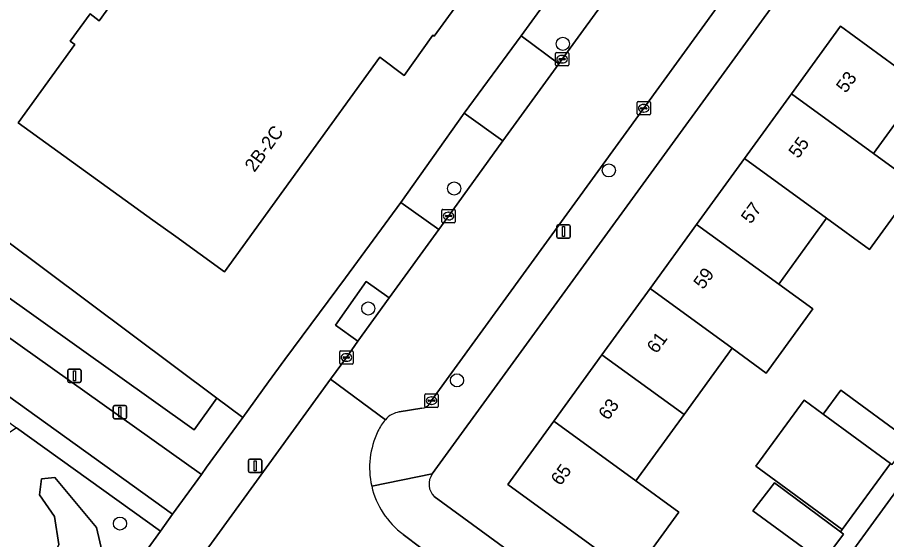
# Model space of a CAD drawing. Extents: x 159674 to 160531, y 382172 to 382904.
# Drawn here: x 160035.6 to 160100.6, y 382527.2 to 382566.2 of the extents above; entities that cross this region are included whole.
import ezdxf

# ---------------------------------------------------------------- set-up
doc = ezdxf.new("R2010")
doc.units = 0
for name, color, linetype in [('IMGEO_Boom', 7, 'Continuous'), ('IMGEO_Erf', 7, 'Continuous'), ('IMGEO_Fietspad_gesloten', 7, 'Continuous'), ('IMGEO_Groenvoorziening', 7, 'Continuous'), ('IMGEO_Kolk', 7, 'Continuous'), ('IMGEO_Lichtmast', 7, 'Continuous'), ('IMGEO_Pand', 7, 'Continuous'), ('IMGEO_Pand_nummerreeks', 7, 'Continuous'), ('IMGEO_Rijbaan_lokaal_open', 7, 'Continuous'), ('IMGEO_Voetpad_open', 7, 'Continuous')]:
    doc.layers.add(name, color=color, linetype=linetype)

msp = doc.modelspace()

# ---------------------------------------------------------------- linework, layer by layer
at = {"layer": 'IMGEO_Boom'}
for centre in [(160076.364, 382564.175), (160079.803, 382554.724), (160068.243, 382553.373), (160061.83, 382544.417), (160068.457, 382539.049), (160043.275, 382528.35)]:
    msp.add_circle(centre, 0.489, dxfattribs=at)
at = {"layer": 'IMGEO_Erf'}
for points in [[(159987.625, 382596.74), (159998.32, 382576.572), (160012.158, 382566.305), (160014.085, 382564.875), (160015.556, 382563.784), (160018.977, 382561.245), (160021.814, 382559.14), (160050.522, 382537.716), (160052.445, 382536.281), (160054.378, 382538.936), (160055.599, 382540.613), (160060.131, 382546.714), (160064.26, 382552.334), (160068.989, 382558.995), (160073.24, 382564.766), (160078.977, 382572.654), (160139.025, 382655.211)], [(160094.261, 382570.107), (160066.611, 382532.056)], [(160068.292, 382566.873), (160066.759, 382564.747), (160066.664, 382564.815), (160064.516, 382561.824), (160062.689, 382563.177), (160051.094, 382547.163), (160047.457, 382549.785), (160045.739, 382551.011), (160035.664, 382558.271), (160039.913, 382564.137), (160039.563, 382564.384), (160041.044, 382566.417), (160041.727, 382565.89), (160044.328, 382569.516)], [(160066.763, 382530.365), (160087.821, 382514.988), (160090.131, 382518.165), (160085.126, 382521.804), (160086.631, 382523.874), (160089.441, 382521.831), (160091.507, 382524.672), (160093.702, 382523.077), (160095.576, 382525.656), (160090.568, 382529.296), (160092.172, 382531.385), (160097.103, 382527.733), (160097.235, 382527.911), (160090.777, 382532.632), (160094.387, 382537.572), (160095.808, 382536.513), (160097.141, 382538.309), (160102.285, 382534.528), (160106.42, 382540.296)], [(160103.851, 382534.341), (160097.038, 382524.967), (160099.595, 382523.109), (160097.556, 382520.304), (160100.009, 382518.521), (160104.902, 382514.966)]]:
    msp.add_lwpolyline(points, dxfattribs=at)
msp.add_lwpolyline([(160099.269, 382548.826), (160096.071, 382551.151), (160092.496, 382546.232), (160095.042, 382544.381), (160091.565, 382539.597), (160089.018, 382541.448), (160085.42, 382536.499), (160081.824, 382531.551), (160085.04, 382529.214), (160081.597, 382524.477), (160078.381, 382526.815), (160072.249, 382531.273), (160075.691, 382536.008), (160079.288, 382540.956), (160082.886, 382545.905), (160086.364, 382550.69), (160089.94, 382555.608), (160093.458, 382560.448), (160097.119, 382565.484), (160103.251, 382561.027), (160099.59, 382555.99), (160102.783, 382553.66)], close=True, dxfattribs=at)
msp.add_arc((160067.66, 382531.298), 1.294, 144.14958, 226.12318, dxfattribs=at)
at = {"layer": 'IMGEO_Fietspad_gesloten'}
msp.add_lwpolyline([(159965.641, 382587.946), (160000, 382563.056), (160014.622, 382552.464), (160047.21, 382529.047), (160049.355, 382532.03), (160024.648, 382549.576), (160016.688, 382555.291), (160013.417, 382557.659), (160011.839, 382558.801), (160000, 382567.372), (159974.626, 382585.74), (159973.843, 382586.307), (159971.861, 382587.698)], dxfattribs=at)
at = {"layer": 'IMGEO_Groenvoorziening'}
for points in [[(160018.977, 382561.245), (160015.556, 382563.784), (160014.917, 382562.902), (160016.424, 382561.811), (160013.417, 382557.659), (160016.688, 382555.291), (160024.648, 382549.576), (160049.355, 382532.03), (160049.733, 382532.555), (160052.445, 382536.281), (160050.522, 382537.716), (160048.808, 382535.362), (160016.765, 382558.19)], [(160018.977, 382561.245), (160016.765, 382558.19), (160048.808, 382535.362), (160050.522, 382537.716), (160021.814, 382559.14)], [(160063.381, 382545.206), (160061.676, 382546.441), (160059.381, 382543.178), (160061.047, 382541.977)], [(160046.298, 382527.781), (160035.555, 382535.501), (160030.156, 382531.864), (160025.451, 382528.695), (160031.388, 382519.807), (160030.964, 382519.524), (160027.973, 382517.526), (160027.284, 382517.066), (160028.729, 382514.78), (160030.117, 382512.584), (160030.328, 382510.79), (160028.033, 382508.833), (160030.233, 382505.553), (160043.699, 382524.182)], [(160038.458, 382522.749), (160039.667, 382522.672), (160041.192, 382523.779), (160042.017, 382525.919), (160041.518, 382528.053), (160038.419, 382531.785), (160037.41, 382531.706), (160037.273, 382530.494), (160038.38, 382528.872), (160038.714, 382526.8), (160037.895, 382525.055), (160038.027, 382523.295)], [(160038.458, 382522.749), (160038.027, 382523.295), (160037.895, 382525.055), (160038.714, 382526.8), (160038.38, 382528.872), (160037.273, 382530.494), (160037.41, 382531.706), (160038.419, 382531.785), (160041.518, 382528.053), (160042.017, 382525.919), (160041.192, 382523.779), (160039.667, 382522.672)]]:
    msp.add_lwpolyline(points, close=True, dxfattribs=at)
at = {"layer": 'IMGEO_Kolk'}
for p, q in [((160075.81, 382562.609), (160075.81, 382563.461)), ((160075.885, 382563.535), (160076.737, 382563.535)), ((160076.069, 382563.029), (160076.069, 382563.041)), ((160076.507, 382562.992), (160076.109, 382562.992)), ((160076.112, 382563.078), (160076.51, 382563.078)), ((160076.298, 382563.315), (160076.323, 382563.315)), ((160076.553, 382563.041), (160076.553, 382563.029)), ((160076.811, 382563.461), (160076.811, 382562.609)), ((160076.737, 382562.535), (160075.885, 382562.535)), ((160076.321, 382562.755), (160076.296, 382562.755)), ((160081.91, 382558.94), (160081.91, 382559.792)), ((160081.985, 382559.866), (160082.837, 382559.866)), ((160082.911, 382559.792), (160082.911, 382558.94)), ((160082.169, 382559.36), (160082.169, 382559.372)), ((160082.607, 382559.323), (160082.209, 382559.323)), ((160082.212, 382559.409), (160082.61, 382559.409)), ((160082.421, 382559.086), (160082.396, 382559.086)), ((160082.398, 382559.646), (160082.423, 382559.646)), ((160082.653, 382559.372), (160082.653, 382559.36)), ((160082.837, 382558.866), (160081.985, 382558.866)), ((160067.328, 382550.891), (160067.328, 382551.743)), ((160067.403, 382551.817), (160068.255, 382551.817)), ((160067.587, 382551.311), (160067.587, 382551.323)), ((160068.025, 382551.274), (160067.627, 382551.274)), ((160067.63, 382551.36), (160068.028, 382551.36)), ((160067.816, 382551.597), (160067.841, 382551.597)), ((160068.071, 382551.323), (160068.071, 382551.311)), ((160068.329, 382551.743), (160068.329, 382550.891)), ((160068.255, 382550.817), (160067.403, 382550.817)), ((160067.839, 382551.037), (160067.814, 382551.037)), ((160059.691, 382540.331), (160059.691, 382541.183)), ((160059.766, 382541.257), (160060.618, 382541.257)), ((160060.179, 382541.037), (160060.204, 382541.037)), ((160060.692, 382541.183), (160060.692, 382540.331)), ((160060.618, 382540.257), (160059.766, 382540.257)), ((160059.95, 382540.751), (160059.95, 382540.763)), ((160060.388, 382540.714), (160059.99, 382540.714)), ((160059.993, 382540.8), (160060.391, 382540.8)), ((160060.202, 382540.477), (160060.177, 382540.477)), ((160060.434, 382540.763), (160060.434, 382540.751)), ((160066.056, 382537.106), (160066.056, 382537.958)), ((160066.131, 382538.032), (160066.983, 382538.032)), ((160066.544, 382537.812), (160066.569, 382537.812)), ((160067.057, 382537.958), (160067.057, 382537.106)), ((160066.983, 382537.032), (160066.131, 382537.032)), ((160066.315, 382537.526), (160066.315, 382537.538)), ((160066.753, 382537.489), (160066.355, 382537.489)), ((160066.358, 382537.575), (160066.756, 382537.575)), ((160066.567, 382537.252), (160066.542, 382537.252)), ((160066.799, 382537.538), (160066.799, 382537.526))]:
    msp.add_line(p, q, dxfattribs=at)
for points in [[(160075.81, 382562.609), (160075.81, 382563.461)], [(160075.885, 382563.535), (160076.737, 382563.535)], [(160076.811, 382563.461), (160076.811, 382562.609)], [(160076.737, 382562.535), (160075.885, 382562.535)], [(160081.91, 382558.94), (160081.91, 382559.792)], [(160081.985, 382559.866), (160082.837, 382559.866)], [(160082.911, 382559.792), (160082.911, 382558.94)], [(160082.837, 382558.866), (160081.985, 382558.866)], [(160067.328, 382550.891), (160067.328, 382551.743)], [(160067.403, 382551.817), (160068.255, 382551.817)], [(160068.329, 382551.743), (160068.329, 382550.891)], [(160068.255, 382550.817), (160067.403, 382550.817)], [(160059.691, 382540.331), (160059.691, 382541.183)], [(160059.766, 382541.257), (160060.618, 382541.257)], [(160060.692, 382541.183), (160060.692, 382540.331)], [(160060.618, 382540.257), (160059.766, 382540.257)], [(160066.056, 382537.106), (160066.056, 382537.958)], [(160066.131, 382538.032), (160066.983, 382538.032)], [(160067.057, 382537.958), (160067.057, 382537.106)], [(160066.983, 382537.032), (160066.131, 382537.032)]]:
    msp.add_lwpolyline(points, dxfattribs=at)
for centre, radius, start, end in [((160075.887, 382563.459), 0.0765, 91.55205, 178.44795), ((160075.887, 382563.459), 0.0765, 91.55205, 178.44795), ((160076.109, 382563.038), 0.0403, 85.87752, 175.75265), ((160076.106, 382563.028), 0.0366, 178.93798, 274.71019), ((160076.51, 382563.035), 0.043, 264.86636, 352.45326), ((160076.514, 382563.04), 0.0386, 1.73085, 96.63898), ((160076.735, 382563.459), 0.0765, 1.55205, 88.44795), ((160076.735, 382563.459), 0.0765, 1.55205, 88.44795), ((160075.887, 382562.611), 0.0765, 181.55205, 268.44795), ((160075.887, 382562.611), 0.0765, 181.55205, 268.44795), ((160076.735, 382562.611), 0.0765, 271.55205, 358.44795), ((160076.735, 382562.611), 0.0765, 271.55205, 358.44795), ((160081.987, 382559.79), 0.0765, 91.55205, 178.44795), ((160081.987, 382559.79), 0.0765, 91.55205, 178.44795), ((160082.835, 382559.79), 0.0765, 1.55205, 88.44795), ((160082.835, 382559.79), 0.0765, 1.55205, 88.44795), ((160082.209, 382559.369), 0.0403, 85.87752, 175.75265), ((160082.206, 382559.359), 0.0366, 178.93798, 274.71019), ((160082.61, 382559.366), 0.043, 264.86636, 352.45326), ((160082.614, 382559.371), 0.0386, 1.73085, 96.63898), ((160081.987, 382558.942), 0.0765, 181.55205, 268.44795), ((160081.987, 382558.942), 0.0765, 181.55205, 268.44795), ((160082.835, 382558.942), 0.0765, 271.55205, 358.44795), ((160082.835, 382558.942), 0.0765, 271.55205, 358.44795), ((160067.405, 382551.741), 0.0765, 91.55205, 178.44795), ((160067.405, 382551.741), 0.0765, 91.55205, 178.44795), ((160067.627, 382551.32), 0.0403, 85.87752, 175.75265), ((160067.624, 382551.31), 0.0366, 178.93798, 274.71019), ((160068.028, 382551.317), 0.043, 264.86636, 352.45326), ((160068.032, 382551.322), 0.0386, 1.73085, 96.63898), ((160068.253, 382551.741), 0.0765, 1.55205, 88.44795), ((160068.253, 382551.741), 0.0765, 1.55205, 88.44795), ((160067.405, 382550.893), 0.0765, 181.55205, 268.44795), ((160067.405, 382550.893), 0.0765, 181.55205, 268.44795), ((160068.253, 382550.893), 0.0765, 271.55205, 358.44795), ((160068.253, 382550.893), 0.0765, 271.55205, 358.44795), ((160059.768, 382541.181), 0.0765, 91.55205, 178.44795), ((160059.768, 382541.181), 0.0765, 91.55205, 178.44795), ((160060.616, 382541.181), 0.0765, 1.55205, 88.44795), ((160060.616, 382541.181), 0.0765, 1.55205, 88.44795), ((160059.768, 382540.333), 0.0765, 181.55205, 268.44795), ((160059.768, 382540.333), 0.0765, 181.55205, 268.44795), ((160059.99, 382540.76), 0.0403, 85.87752, 175.75265), ((160059.987, 382540.75), 0.0366, 178.93798, 274.71019), ((160060.391, 382540.757), 0.043, 264.86636, 352.45326), ((160060.395, 382540.762), 0.0386, 1.73085, 96.63898), ((160060.616, 382540.333), 0.0765, 271.55205, 358.44795), ((160060.616, 382540.333), 0.0765, 271.55205, 358.44795), ((160066.133, 382537.956), 0.0765, 91.55205, 178.44795), ((160066.133, 382537.956), 0.0765, 91.55205, 178.44795), ((160066.981, 382537.956), 0.0765, 1.55205, 88.44795), ((160066.981, 382537.956), 0.0765, 1.55205, 88.44795), ((160066.133, 382537.108), 0.0765, 181.55205, 268.44795), ((160066.133, 382537.108), 0.0765, 181.55205, 268.44795), ((160066.355, 382537.535), 0.0403, 85.87752, 175.75265), ((160066.352, 382537.525), 0.0366, 178.93798, 274.71019), ((160066.756, 382537.532), 0.043, 264.86636, 352.45326), ((160066.76, 382537.537), 0.0386, 1.73085, 96.63898), ((160066.981, 382537.108), 0.0765, 271.55205, 358.44795), ((160066.981, 382537.108), 0.0765, 271.55205, 358.44795)]:
    msp.add_arc(centre, radius, start, end, dxfattribs=at)
for centre, major_axis, ratio, start_param, end_param in [((160076.297, 382563.035), (-0.387, 0.002), 0.722429, 4.712389, 7.853982), ((160076.322, 382563.035), (-0.39, 0.002), 0.717154, 1.570796, 4.712389), ((160082.397, 382559.366), (-0.387, 0.002), 0.722429, 4.712389, 7.853982), ((160082.422, 382559.366), (-0.39, 0.002), 0.717154, 1.570796, 4.712389), ((160067.815, 382551.317), (-0.387, 0.002), 0.722429, 4.712389, 7.853982), ((160067.84, 382551.317), (-0.39, 0.002), 0.717154, 1.570796, 4.712389), ((160060.178, 382540.757), (-0.387, 0.002), 0.722429, 4.712389, 7.853982), ((160060.203, 382540.757), (-0.39, 0.002), 0.717154, 1.570796, 4.712389), ((160066.543, 382537.532), (-0.387, 0.002), 0.722429, 4.712389, 7.853982), ((160066.568, 382537.532), (-0.39, 0.002), 0.717154, 1.570796, 4.712389)]:
    msp.add_ellipse(centre, major_axis=major_axis, ratio=ratio, start_param=start_param, end_param=end_param, dxfattribs=at)
at = {"layer": 'IMGEO_Lichtmast'}
for p, q in [((160076.018, 382550.665), (160076.808, 382550.665)), ((160076.808, 382550.665), (160076.018, 382550.665)), ((160075.918, 382549.765), (160075.918, 382550.565)), ((160075.918, 382550.565), (160075.918, 382549.765)), ((160076.908, 382550.565), (160076.908, 382549.765)), ((160076.908, 382549.765), (160076.908, 382550.565)), ((160076.808, 382549.665), (160076.018, 382549.665)), ((160076.018, 382549.665), (160076.808, 382549.665)), ((160039.375, 382538.987), (160039.375, 382539.787)), ((160039.375, 382539.787), (160039.375, 382538.987)), ((160039.475, 382539.887), (160040.265, 382539.887)), ((160040.265, 382539.887), (160039.475, 382539.887)), ((160040.365, 382539.787), (160040.365, 382538.987)), ((160040.365, 382538.987), (160040.365, 382539.787)), ((160040.265, 382538.887), (160039.475, 382538.887)), ((160039.475, 382538.887), (160040.265, 382538.887)), ((160042.778, 382536.278), (160042.778, 382537.078)), ((160042.778, 382537.078), (160042.778, 382536.278)), ((160042.878, 382537.178), (160043.668, 382537.178)), ((160043.668, 382537.178), (160042.878, 382537.178)), ((160043.768, 382537.078), (160043.768, 382536.278)), ((160043.768, 382536.278), (160043.768, 382537.078)), ((160043.668, 382536.178), (160042.878, 382536.178)), ((160042.878, 382536.178), (160043.668, 382536.178)), ((160052.874, 382532.263), (160052.874, 382533.063)), ((160052.874, 382533.063), (160052.874, 382532.263)), ((160052.974, 382533.163), (160053.764, 382533.163)), ((160053.764, 382533.163), (160052.974, 382533.163)), ((160053.864, 382533.063), (160053.864, 382532.263)), ((160053.864, 382532.263), (160053.864, 382533.063)), ((160053.764, 382532.163), (160052.974, 382532.163)), ((160052.974, 382532.163), (160053.764, 382532.163))]:
    msp.add_line(p, q, dxfattribs=at)
for points in [[(160076.338, 382550.54), (160076.488, 382550.54), (160076.488, 382549.79), (160076.338, 382549.79), (160076.338, 382550.54)], [(160039.795, 382539.762), (160039.945, 382539.762), (160039.945, 382539.012), (160039.795, 382539.012), (160039.795, 382539.762)], [(160043.198, 382537.053), (160043.348, 382537.053), (160043.348, 382536.303), (160043.198, 382536.303), (160043.198, 382537.053)], [(160053.294, 382533.038), (160053.444, 382533.038), (160053.444, 382532.288), (160053.294, 382532.288), (160053.294, 382533.038)]]:
    msp.add_lwpolyline(points, dxfattribs=at)
for centre, start, end in [((160076.018, 382550.565), 90, 180), ((160076.018, 382550.565), 90, 180), ((160076.808, 382550.565), 0, 90), ((160076.808, 382550.565), 360, 90), ((160076.018, 382549.765), 180, 270), ((160076.018, 382549.765), 180, 270), ((160076.808, 382549.765), 270, 0), ((160076.808, 382549.765), 270, 0), ((160039.475, 382539.787), 90, 180), ((160039.475, 382539.787), 90, 180), ((160040.265, 382539.787), 0, 90), ((160040.265, 382539.787), 360, 90), ((160039.475, 382538.987), 180, 270), ((160039.475, 382538.987), 180, 270), ((160040.265, 382538.987), 270, 0), ((160040.265, 382538.987), 270, 0), ((160042.878, 382537.078), 90, 180), ((160042.878, 382537.078), 90, 180), ((160043.668, 382537.078), 0, 90), ((160043.668, 382537.078), 360, 90), ((160042.878, 382536.278), 180, 270), ((160042.878, 382536.278), 180, 270), ((160043.668, 382536.278), 270, 0), ((160043.668, 382536.278), 270, 0), ((160052.974, 382533.063), 90, 180), ((160052.974, 382533.063), 90, 180), ((160053.764, 382533.063), 0, 90), ((160053.764, 382533.063), 360, 90), ((160052.974, 382532.263), 180, 270), ((160052.974, 382532.263), 180, 270), ((160053.764, 382532.263), 270, 0), ((160053.764, 382532.263), 270, 0)]:
    msp.add_arc(centre, 0.1, start, end, dxfattribs=at)
at = {"layer": 'IMGEO_Pand'}
msp.add_lwpolyline([(160044.328, 382569.516), (160041.727, 382565.89), (160041.044, 382566.417), (160039.563, 382564.384), (160039.913, 382564.137), (160035.664, 382558.271), (160045.739, 382551.011), (160047.457, 382549.785), (160051.094, 382547.163), (160062.689, 382563.177), (160064.516, 382561.824), (160066.664, 382564.815), (160066.759, 382564.747), (160068.292, 382566.873)], dxfattribs=at)
for points in [[(160099.59, 382555.99), (160103.251, 382561.027), (160097.119, 382565.484), (160093.458, 382560.448)], [(160099.59, 382555.99), (160093.458, 382560.448), (160089.94, 382555.608), (160096.071, 382551.151), (160099.269, 382548.826), (160102.783, 382553.66)], [(160096.071, 382551.151), (160089.94, 382555.608), (160086.364, 382550.69), (160092.496, 382546.232)], [(160092.496, 382546.232), (160086.364, 382550.69), (160082.886, 382545.905), (160089.018, 382541.448), (160091.565, 382539.597), (160095.042, 382544.381)], [(160085.42, 382536.499), (160089.018, 382541.448), (160082.886, 382545.905), (160079.288, 382540.956)], [(160085.42, 382536.499), (160079.288, 382540.956), (160075.691, 382536.008), (160081.824, 382531.551)], [(160100.846, 382532.851), (160100.973, 382532.759), (160102.285, 382534.528), (160097.141, 382538.309), (160095.808, 382536.513)], [(160100.846, 382532.851), (160095.808, 382536.513), (160094.387, 382537.572), (160090.777, 382532.632), (160097.235, 382527.911)], [(160081.824, 382531.551), (160075.691, 382536.008), (160072.249, 382531.273), (160078.381, 382526.815), (160081.597, 382524.477), (160085.04, 382529.214)], [(160092.172, 382531.385), (160090.568, 382529.296), (160095.576, 382525.656), (160095.8, 382525.493), (160097.338, 382527.559), (160097.103, 382527.733)]]:
    msp.add_lwpolyline(points, close=True, dxfattribs=at)
at = {"layer": 'IMGEO_Rijbaan_lokaal_open'}
for points in [[(160102.443, 382586.988), (160126.918, 382620.636), (160127.333, 382621.232), (160121.569, 382625.329), (160121.488, 382625.214), (160109.443, 382608.67), (160097.463, 382592.089), (160084.229, 382573.928), (160076.311, 382563.035), (160076.064, 382562.694), (160071.89, 382556.928), (160067.829, 382551.317), (160067.089, 382550.301), (160063.381, 382545.206), (160061.047, 382541.977), (160060.192, 382540.757), (160059.002, 382539.131), (160063.104, 382536.111)], [(160066.449, 382537.355), (160066.557, 382537.532), (160082.411, 382559.366), (160090.741, 382570.837)], [(160063.104, 382536.111), (160059.002, 382539.131), (160047.551, 382523.358), (160051.746, 382520.454)], [(160064.148, 382536.686), (160065.82, 382536.96)], [(160060.275, 382521.826), (160061.728, 382520.822), (160065.761, 382526.548), (160064.445, 382527.55)]]:
    msp.add_lwpolyline(points, dxfattribs=at)
for centre, radius, start, end in [((160065.729, 382537.803), 0.848, 276.1682, 328.08787), ((160064.422, 382534.954), 1.754, 98.97892, 138.71006), ((160065.777, 382533.796), 3.536, 139.10008, 155.69925), ((160068.118, 382532.535), 6.191, 153.98074, 192.90949), ((160068.122, 382532.537), 6.196, 192.91404, 233.59543)]:
    msp.add_arc(centre, radius, start, end, dxfattribs=at)
at = {"layer": 'IMGEO_Voetpad_open'}
for points in [[(160160.682, 382684.114), (160158.819, 382681.732), (160139.364, 382654.969), (160139.025, 382655.211), (160078.977, 382572.654), (160073.24, 382564.766), (160076.064, 382562.694), (160076.311, 382563.035), (160084.229, 382573.928), (160097.463, 382592.089), (160109.443, 382608.67), (160121.488, 382625.214), (160121.569, 382625.329), (160133.916, 382642.352), (160134.723, 382643.445), (160146.792, 382660.104), (160161.775, 382680.602)], [(159964.799, 382586.692), (159967.51, 382584.743), (159970.845, 382582.345), (160000, 382561.222), (160009.525, 382554.321), (160011.589, 382552.825), (160013.763, 382551.289), (160017.06, 382548.87), (160020.045, 382546.68), (160022.267, 382545.049), (160034.271, 382536.423), (160035.555, 382535.501), (160046.298, 382527.781), (160047.21, 382529.047), (160014.622, 382552.464), (160000, 382563.056), (159965.641, 382587.946)], [(160090.741, 382570.837), (160082.411, 382559.366), (160066.557, 382537.532), (160066.449, 382537.355)], [(160062.083, 382531.152), (160066.611, 382532.056), (160094.261, 382570.107)], [(160047.551, 382523.358), (160059.002, 382539.131), (160060.192, 382540.757), (160061.047, 382541.977), (160059.381, 382543.178), (160061.676, 382546.441), (160063.381, 382545.206), (160067.089, 382550.301), (160064.26, 382552.334), (160060.131, 382546.714), (160055.599, 382540.613), (160054.378, 382538.936), (160052.445, 382536.281), (160049.733, 382532.555), (160049.355, 382532.03), (160047.21, 382529.047), (160046.298, 382527.781), (160043.699, 382524.182)], [(160065.82, 382536.96), (160064.148, 382536.686)], [(160100.846, 382532.851), (160097.235, 382527.911), (160097.103, 382527.733), (160097.338, 382527.559), (160095.8, 382525.493), (160095.576, 382525.656), (160093.702, 382523.077), (160090.131, 382518.165), (160087.821, 382514.988), (160089.124, 382514.036), (160090.673, 382516.21), (160093.613, 382520.255), (160097.038, 382524.967), (160103.851, 382534.341)], [(160066.611, 382532.056), (160062.083, 382531.152)], [(160088.55, 382513.229), (160089.124, 382514.036), (160087.821, 382514.988), (160066.763, 382530.365)], [(160064.445, 382527.55), (160065.761, 382526.548), (160066.041, 382526.373), (160086.083, 382511.782), (160148.312, 382466.705), (160171.029, 382450.249)]]:
    msp.add_lwpolyline(points, dxfattribs=at)
for points in [[(160076.064, 382562.694), (160073.24, 382564.766), (160068.989, 382558.995), (160071.89, 382556.928)], [(160071.89, 382556.928), (160068.989, 382558.995), (160064.26, 382552.334), (160067.089, 382550.301), (160067.829, 382551.317)]]:
    msp.add_lwpolyline(points, close=True, dxfattribs=at)
for centre, radius, start, end in [((160065.729, 382537.803), 0.848, 276.1682, 328.08787), ((160064.422, 382534.954), 1.754, 98.97892, 138.71006), ((160065.777, 382533.796), 3.536, 139.10008, 155.69925), ((160068.118, 382532.535), 6.191, 153.98074, 192.90949), ((160067.66, 382531.298), 1.294, 144.14958, 226.12318), ((160068.122, 382532.537), 6.196, 192.91404, 233.59543)]:
    msp.add_arc(centre, radius, start, end, dxfattribs=at)

# ---------------------------------------------------------------- texts
at = {"layer": 'IMGEO_Pand_nummerreeks'}
for s, rotation, p in [('53', 53.98438, (160097.51, 382560.443)), ('2B-2C', 54.09343, (160053.322, 382554.536)), ('55', 53.98408, (160093.956, 382555.556)), ('57', 53.98438, (160090.405, 382550.669)), ('59', 53.98408, (160086.851, 382545.781)), ('61', 53.98438, (160083.365, 382540.985)), ('63', 53.98438, (160079.746, 382536.007)), ('65', 53.98408, (160076.192, 382531.119))]:
    msp.add_text(s, height=1, rotation=rotation, dxfattribs=at).set_placement(p)

doc.saveas('drawing.dxf')
